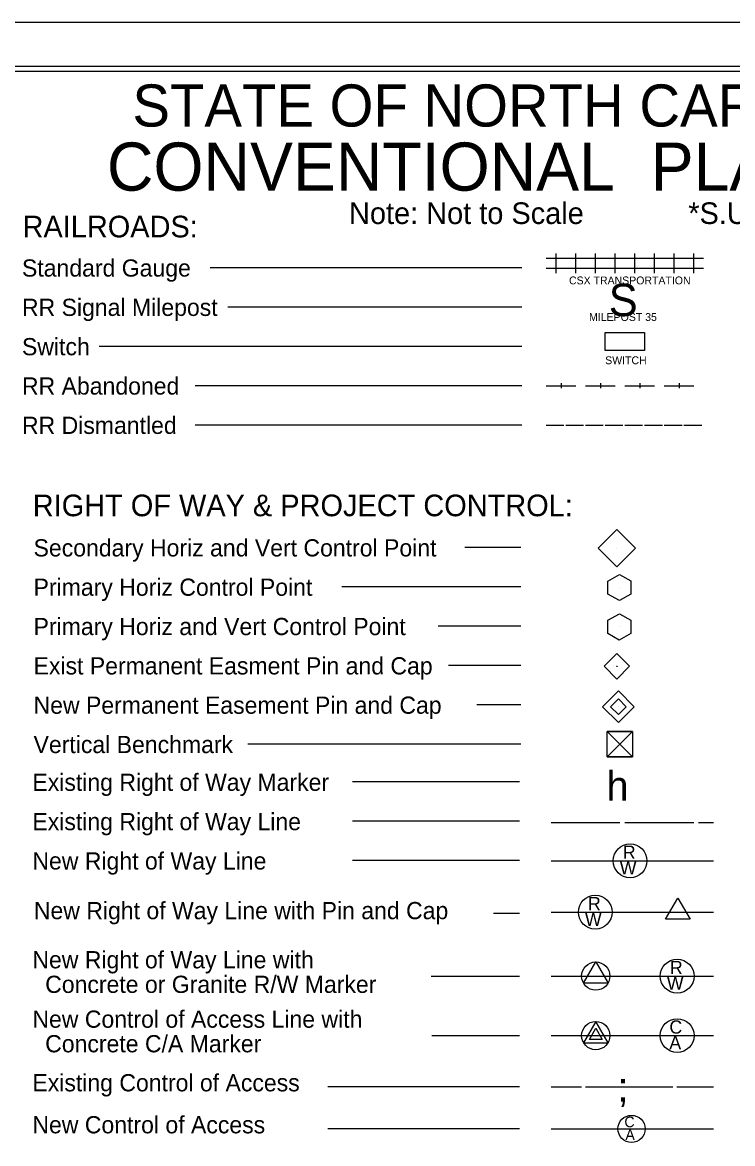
# Model space of a CAD drawing. Extents: x 1729989.5 to 1730023.2, y 539942.1 to 539964.1.
# Drawn here: x 1730000.76 to 1730007.99, y 539952.69 to 539964.1 of the extents above; entities that cross this region are included whole.
import ezdxf

# ---------------------------------------------------------------- set-up
doc = ezdxf.new("R2010")
doc.units = 0
for name, color, linetype in [('Default', 7, 'Continuous'), ('Prop ROW Permanent Easement CELL', 7, 'Continuous'), ('Sheet Cutting Line CELL', 7, 'Continuous'), ('Sheet Plot Border Inside CELL', 7, 'Continuous'), ('Sheet Plot Border Outside CELL', 7, 'Continuous'), ('Sheet Symbology CELL', 7, 'Continuous')]:
    doc.layers.add(name, color=color, linetype=linetype)

msp = doc.modelspace()

# ---------------------------------------------------------------- linework, layer by layer
at = {"layer": 'Default'}
for p, q in [((1730006.808, 539958.75), (1730006.808, 539958.75)), ((1730006.834, 539958.35), (1730006.834, 539958.35)), ((1730006.834, 539957.95), (1730006.834, 539957.95)), ((1730006.809, 539957.549), (1730006.809, 539957.549)), ((1730006.839, 539956.758), (1730006.839, 539956.758))]:
    msp.add_line(p, q, dxfattribs=at)
for points in [[(1730006.62, 539958.751), (1730006.809, 539958.94), (1730006.998, 539958.75), (1730006.809, 539958.561)], [(1730006.717, 539958.017), (1730006.835, 539958.083), (1730006.952, 539958.018), (1730006.95, 539957.884), (1730006.833, 539957.816), (1730006.717, 539957.881)], [(1730006.679, 539957.549), (1730006.809, 539957.679), (1730006.938, 539957.549), (1730006.809, 539957.419)], [(1730006.709, 539956.887), (1730006.968, 539956.887), (1730006.968, 539956.628), (1730006.709, 539956.628)]]:
    msp.add_lwpolyline(points, close=True, dxfattribs=at)
for points in [[(1730006.834, 539958.217), (1730006.718, 539958.283), (1730006.718, 539958.416), (1730006.834, 539958.483), (1730006.95, 539958.417), (1730006.95, 539958.283), (1730006.834, 539958.217)], [(1730006.968, 539956.887), (1730006.709, 539956.628), (1730006.839, 539956.758), (1730006.968, 539956.628), (1730006.709, 539956.887)], [(1730006.839, 539956.758), (1730006.968, 539956.887), (1730006.709, 539956.887), (1730006.839, 539956.758)], [(1730006.839, 539956.758), (1730006.709, 539956.628), (1730006.968, 539956.628), (1730006.839, 539956.758)]]:
    msp.add_lwpolyline(points, dxfattribs=at)
msp.add_circle((1730006.809, 539957.549), 0.00253, dxfattribs=at)
at = {"layer": 'Prop ROW Permanent Easement CELL'}
msp.add_line((1730006.824, 539957.138), (1730006.824, 539957.138), dxfattribs=at)
for points in [[(1730006.824, 539957.299), (1730006.985, 539957.138), (1730006.824, 539956.977), (1730006.663, 539957.138)], [(1730006.824, 539957.219), (1730006.904, 539957.138), (1730006.824, 539957.058), (1730006.743, 539957.138)]]:
    msp.add_lwpolyline(points, close=True, dxfattribs=at)
at = {"layer": 'Sheet Cutting Line CELL'}
msp.add_line((1730023.211, 539964.097), (1729989.531, 539964.097), dxfattribs=at)
at = {"layer": 'Sheet Plot Border Inside CELL'}
msp.add_lwpolyline([(1729989.791, 539942.546), (1730023.121, 539942.546), (1730023.121, 539963.648), (1729989.791, 539963.648)], close=True, dxfattribs=at)
at = {"layer": 'Sheet Plot Border Outside CELL'}
msp.add_lwpolyline([(1729989.531, 539942.097), (1730023.211, 539942.097), (1730023.211, 539964.097), (1729989.531, 539964.097)], close=True, dxfattribs=at)
at = {"layer": 'Sheet Symbology CELL'}
for p, q in [((1730006.191, 539961.548), (1730006.191, 539961.748)), ((1730006.391, 539961.548), (1730006.391, 539961.748)), ((1730006.591, 539961.548), (1730006.591, 539961.748)), ((1730006.791, 539961.548), (1730006.791, 539961.748)), ((1730006.991, 539961.548), (1730006.991, 539961.748)), ((1730007.191, 539961.548), (1730007.191, 539961.748)), ((1730007.391, 539961.548), (1730007.391, 539961.748)), ((1730007.591, 539961.548), (1730007.591, 539961.748)), ((1730006.091, 539961.698), (1730006.291, 539961.698)), ((1730006.291, 539961.698), (1730006.491, 539961.698)), ((1730006.491, 539961.698), (1730006.691, 539961.698)), ((1730006.691, 539961.698), (1730006.891, 539961.698)), ((1730006.891, 539961.698), (1730007.091, 539961.698)), ((1730007.091, 539961.698), (1730007.291, 539961.698)), ((1730007.291, 539961.698), (1730007.491, 539961.698)), ((1730007.491, 539961.698), (1730007.691, 539961.698)), ((1730005.843, 539961.602), (1730002.674, 539961.602)), ((1730006.091, 539961.598), (1730006.291, 539961.598)), ((1730006.291, 539961.598), (1730006.491, 539961.598)), ((1730006.491, 539961.598), (1730006.691, 539961.598)), ((1730006.691, 539961.598), (1730006.891, 539961.598)), ((1730006.891, 539961.598), (1730007.091, 539961.598)), ((1730007.091, 539961.598), (1730007.291, 539961.598)), ((1730007.291, 539961.598), (1730007.491, 539961.598)), ((1730007.491, 539961.598), (1730007.691, 539961.598)), ((1730005.843, 539961.202), (1730002.852, 539961.202)), ((1730005.843, 539960.802), (1730001.544, 539960.802)), ((1730005.843, 539960.402), (1730002.519, 539960.402)), ((1730006.091, 539960.402), (1730006.391, 539960.402)), ((1730006.241, 539960.427), (1730006.241, 539960.377)), ((1730006.491, 539960.402), (1730006.791, 539960.402)), ((1730006.641, 539960.427), (1730006.641, 539960.377)), ((1730006.891, 539960.402), (1730007.191, 539960.402)), ((1730007.041, 539960.427), (1730007.041, 539960.377)), ((1730007.291, 539960.402), (1730007.591, 539960.402)), ((1730007.441, 539960.427), (1730007.441, 539960.377)), ((1730005.843, 539960.002), (1730002.519, 539960.002)), ((1730005.843, 539960.002), (1730002.519, 539960.002)), ((1730006.091, 539960.002), (1730006.271, 539960.002)), ((1730006.291, 539960.002), (1730006.471, 539960.002)), ((1730006.491, 539960.002), (1730006.671, 539960.002)), ((1730006.691, 539960.002), (1730006.871, 539960.002)), ((1730006.891, 539960.002), (1730007.071, 539960.002)), ((1730007.091, 539960.002), (1730007.271, 539960.002)), ((1730007.291, 539960.002), (1730007.471, 539960.002)), ((1730007.491, 539960.002), (1730007.671, 539960.002)), ((1730005.832, 539958.757), (1730005.261, 539958.757)), ((1730005.832, 539958.357), (1730004.011, 539958.357)), ((1730005.832, 539957.957), (1730004.993, 539957.957)), ((1730005.832, 539957.557), (1730005.098, 539957.557)), ((1730005.832, 539957.157), (1730005.385, 539957.157)), ((1730005.832, 539956.757), (1730003.055, 539956.757)), ((1730005.82, 539956.373), (1730004.121, 539956.373)), ((1730005.82, 539955.973), (1730004.121, 539955.973)), ((1730006.14, 539955.961), (1730006.84, 539955.961)), ((1730006.89, 539955.961), (1730007.59, 539955.961)), ((1730007.64, 539955.961), (1730007.79, 539955.961)), ((1730005.82, 539955.573), (1730004.121, 539955.573)), ((1730006.14, 539955.57), (1730007.79, 539955.57)), ((1730005.82, 539955.036), (1730005.555, 539955.036)), ((1730006.14, 539955.048), (1730007.79, 539955.048)), ((1730007.429, 539955.048), (1730007.429, 539955.048)), ((1730005.82, 539954.395), (1730004.92, 539954.395)), ((1730006.14, 539954.398), (1730007.79, 539954.398)), ((1730006.594, 539954.398), (1730006.594, 539954.398)), ((1730005.82, 539953.79), (1730004.928, 539953.79)), ((1730006.14, 539953.793), (1730007.79, 539953.793)), ((1730006.594, 539953.793), (1730006.594, 539953.793)), ((1730005.82, 539953.271), (1730003.869, 539953.271)), ((1730006.14, 539953.271), (1730006.45, 539953.271)), ((1730006.49, 539953.271), (1730007.378, 539953.271)), ((1730007.418, 539953.271), (1730007.79, 539953.271)), ((1730005.82, 539952.844), (1730003.869, 539952.844)), ((1730006.14, 539952.844), (1730007.79, 539952.844))]:
    msp.add_line(p, q, dxfattribs=at)
for points in [[(1730022.871, 539963.597), (1729992.871, 539963.597), (1729992.871, 539942.617), (1730022.871, 539942.617)], [(1730006.691, 539960.942), (1730007.091, 539960.942), (1730007.091, 539960.76), (1730006.691, 539960.76)], [(1730007.304, 539954.976), (1730007.429, 539955.192), (1730007.554, 539954.976)], [(1730006.469, 539954.326), (1730006.594, 539954.542), (1730006.719, 539954.326)], [(1730006.469, 539953.721), (1730006.719, 539953.721), (1730006.594, 539953.937)], [(1730006.529, 539953.755), (1730006.594, 539953.868), (1730006.66, 539953.755)]]:
    msp.add_lwpolyline(points, close=True, dxfattribs=at)
for centre, radius in [((1730006.943, 539955.57), 0.172), ((1730006.589, 539955.048), 0.172), ((1730007.422, 539954.398), 0.172), ((1730006.594, 539954.398), 0.144), ((1730006.594, 539953.793), 0.144), ((1730007.422, 539953.793), 0.172), ((1730006.958, 539952.844), 0.138)]:
    msp.add_circle(centre, radius, dxfattribs=at)

# ---------------------------------------------------------------- texts
for s, height, p in [('STATE OF NORTH CAROLINA, DIVISION OF HIGHWAYS', 0.42838, (1730001.882, 539963.038)), ('CONVENTIONAL  PLAN SHEET SYMBOLS', 0.48961, (1730001.623, 539962.386)), ('RAILROADS:', 0.22, (1730000.765, 539961.911)), ('Standard Gauge', 0.175, (1730000.759, 539961.512)), ('S', 0.33, (1730006.726, 539961.11)), ('RR Signal Milepost', 0.175, (1730000.759, 539961.112)), ('Switch', 0.175, (1730000.759, 539960.712)), ('RR Abandoned', 0.175, (1730000.759, 539960.312)), ('RR Dismantled', 0.175, (1730000.759, 539959.912)), ('RIGHT OF WAY & PROJECT CONTROL:', 0.22, (1730000.869, 539959.075)), ('Secondary Horiz and Vert Control Point', 0.175, (1730000.877, 539958.666)), ('Primary Horiz Control Point', 0.175, (1730000.877, 539958.266)), ('Primary Horiz and Vert Control Point', 0.175, (1730000.877, 539957.866)), ('Exist Permanent Easment Pin and Cap', 0.175, (1730000.877, 539957.466)), ('New Permanent Easement Pin and Cap', 0.175, (1730000.877, 539957.066)), ('Vertical Benchmark', 0.175, (1730000.877, 539956.666)), ('h', 0.3, (1730006.704, 539956.182)), ('Existing Right of Way Marker', 0.175, (1730000.865, 539956.282)), ('Existing Right of Way Line', 0.175, (1730000.865, 539955.882)), ('R', 0.135, (1730006.869, 539955.591)), ('New Right of Way Line', 0.175, (1730000.865, 539955.482)), ('W', 0.135, (1730006.838, 539955.432)), ('New Right of Way Line with Pin and Cap', 0.175, (1730000.88, 539954.977)), ('R', 0.135, (1730006.515, 539955.068)), ('W', 0.135, (1730006.484, 539954.909)), ('New Right of Way Line with', 0.175, (1730000.865, 539954.477)), ('R', 0.135, (1730007.348, 539954.418)), ('  Concrete or Granite R/W Marker', 0.175, (1730000.865, 539954.227)), ('W', 0.135, (1730007.317, 539954.259)), ('New Control of Access Line with', 0.175, (1730000.865, 539953.873)), ('C', 0.135, (1730007.343, 539953.813)), ('  Concrete C/A Marker', 0.175, (1730000.865, 539953.623)), ('A', 0.135, (1730007.342, 539953.654)), ('Existing Control of Access', 0.175, (1730000.865, 539953.226)), (';', 0.3, (1730006.815, 539953.121)), ('New Control of Access', 0.175, (1730000.865, 539952.799)), ('C', 0.108, (1730006.885, 539952.861)), ('A', 0.108, (1730006.895, 539952.731))]:
    msp.add_text(s, height=height, dxfattribs=at).set_placement(p)
for s, height, p in [('Note: Not to Scale', 0.22, (1730004.085, 539962.047)), ('*S.U.E. = Subsurface Utility Engineering', 0.22, (1730007.535, 539962.047)), ('CSX TRANSPORTATION', 0.08, (1730006.322, 539961.433)), ('MILEPOST 35', 0.08, (1730006.526, 539961.061)), ('SWITCH', 0.08, (1730006.69, 539960.621))]:
    msp.add_text(s, height=height, rotation=360, dxfattribs=at).set_placement(p)

doc.saveas('drawing.dxf')
